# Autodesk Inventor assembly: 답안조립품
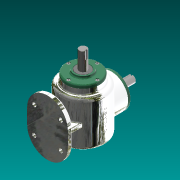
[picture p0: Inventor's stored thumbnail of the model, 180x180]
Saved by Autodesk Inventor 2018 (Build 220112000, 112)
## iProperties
Created: 2023-01
Part Number: 답안조립품
Material: 일반
Document SubType Name: Assembly
Designer: 강의실01
Author: 강의실01
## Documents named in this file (14)
- C:\Users\kimgi\Desktop\730106V1011\답안조립품.iam
- C:\Users\kimgi\Desktop\730106V1011\본체.ipt
- C:\Users\kimgi\Desktop\730106V1011\커버.ipt
- C:\Users\kimgi\Desktop\730106V1011\베어링 6203.ipt
- C:\Users\kimgi\Desktop\730106V1011\메인 축.ipt
- 메인 축.ipt
- C:\Users\kimgi\Desktop\730106V1011\서브 축.ipt
- 서브 축.ipt
- C:\Users\kimgi\Desktop\730106V1011\키 5x5.ipt
- C:\Users\kimgi\Desktop\730106V1011\키 4x4.ipt
- C:\Users\kimgi\Desktop\730106V1011\오일실 17 32 8.ipt
- C:\Users\kimgi\Desktop\730106V1011\메인 베벨기어.ipt
- C:\Users\kimgi\Desktop\730106V1011\서브 베벨기어.ipt
- C:\Users\kimgi\Desktop\730106V1011\M4.ipt
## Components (8 placed, 1 different names)
1. M4:1
2. M4:2
3. M4:3
4. M4:4
5. M4:5
6. M4:6
7. M4:7
8. M4:8
